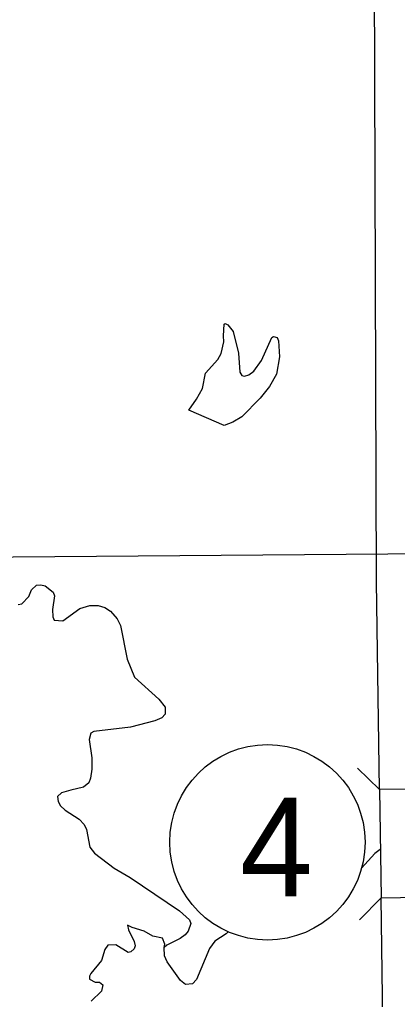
# Model space of a CAD drawing. Extents: x 982240 to 1103002, y 974866 to 1054902.
# Drawn here: x 1055765 to 1057609, y 1005692 to 1010471 of the extents above; entities that cross this region are included whole.
import ezdxf

# ---------------------------------------------------------------- set-up
doc = ezdxf.new("R2010")
doc.units = 0
for name, color, linetype in [('10', 7, 'Continuous'), ('35', 7, 'Continuous'), ('37', 7, 'Continuous'), ('5', 7, 'Continuous'), ('R_Draft', 7, 'Continuous')]:
    doc.layers.add(name, color=color, linetype=linetype)

msp = doc.modelspace()

# ---------------------------------------------------------------- linework, layer by layer
at = {"layer": '10'}
for p, q in [((1057771.9, 1006719.4), (1057521.9, 1006715.5)), ((1057529.2, 1006187.7), (1057779.2, 1006191.7))]:
    msp.add_line(p, q, dxfattribs=at)
for points in [[(1057521.9, 1006715.5), (1057507.8, 1007729.5), (1057490.8, 1012651.9), (1057440.6, 1017897.7), (1057430.5, 1017929.5), (1057356.9, 1018048.7)], [(1057521.9, 1006715.5), (1057529.2, 1006187.7)], [(1057577.8, 1002687.5), (1057529.2, 1006187.7)]]:
    msp.add_lwpolyline(points, dxfattribs=at)
at = {"layer": '35'}
for points in [[(1056591.5, 1008565.5), (1056629.2, 1008619.6), (1056657, 1008672.5), (1056672.3, 1008747.2), (1056732.8, 1008812.9), (1056749.2, 1008842.4), (1056761.8, 1008900), (1056760.1, 1008929.1), (1056762.8, 1008985.4), (1056768.7, 1008988.5), (1056780.9, 1008982.8), (1056806.7, 1008950.3), (1056834.3, 1008844.5), (1056839.5, 1008752.2), (1056850, 1008734.4), (1056863.1, 1008732.7), (1056883.9, 1008739.2), (1056907.6, 1008756.8), (1056946.4, 1008808), (1056996.8, 1008920.7), (1057004.8, 1008924.9), (1057022.9, 1008920.3), (1057029.3, 1008904.4), (1057034.2, 1008826.1), (1057019.2, 1008742.4), (1056985.6, 1008681.4), (1056938.8, 1008624), (1056849.8, 1008533.5), (1056805.3, 1008507.3), (1056763.6, 1008491.2)], [(1056763.6, 1008491.2), (1056591.5, 1008565.5)], [(1055758.3, 1007618.4), (1055775.2, 1007621.9), (1055810.5, 1007656.9), (1055823.7, 1007689.3), (1055847.2, 1007712), (1055868.2, 1007714.5), (1055890.4, 1007709), (1055928.2, 1007678.8), (1055935.7, 1007659.9), (1055926.2, 1007594.3), (1055927.1, 1007558.2), (1055934.5, 1007542.3), (1055975.7, 1007538.3), (1056059.4, 1007599.5), (1056108.2, 1007612.8), (1056148.3, 1007613.7), (1056180.6, 1007604.5), (1056209.1, 1007586.1), (1056241, 1007548.7), (1056257.9, 1007515.9), (1056289.9, 1007352), (1056325.1, 1007263.4), (1056443.9, 1007156.8), (1056475.9, 1007117.4), (1056475.7, 1007084.2), (1056460.1, 1007065.8), (1056424.4, 1007050.8), (1056305.9, 1007019.9), (1056128, 1006998.6), (1056113.1, 1006991.2), (1056103.9, 1006959.8), (1056118, 1006869.8), (1056117.3, 1006815.5), (1056111.4, 1006772.2), (1056102.9, 1006748.9), (1056077.4, 1006727.2), (1056014.6, 1006713.6), (1055968.8, 1006699.5), (1055950.2, 1006681.9), (1055952.8, 1006657.9), (1055965.3, 1006636.1), (1055987.8, 1006615.5), (1056055.1, 1006570.9), (1056080.7, 1006545.4), (1056091.3, 1006521.6), (1056108.4, 1006435.6), (1056130.2, 1006405), (1056226.2, 1006333), (1056304.4, 1006287.7)], [(1057525.6, 1006423.8), (1057498.3, 1006404.6), (1057433.9, 1006332.8), (1057433.5, 1006332.6)], [(1056304.4, 1006287.7), (1056544.9, 1006123.7), (1056595, 1006080.7), (1056600.5, 1006062.7), (1056588.3, 1006025.3), (1056573.8, 1006006.8), (1056549.1, 1005989.2), (1056483.7, 1005957.5), (1056470, 1005946.1), (1056473.6, 1005962.3), (1056462.9, 1005991.1), (1056415.5, 1006001), (1056372.9, 1006025.1), (1056315.3, 1006043.8), (1056292, 1006054.3), (1056296.5, 1006032.3), (1056324, 1005974.8), (1056329.5, 1005953.8), (1056323.8, 1005938.6), (1056308.1, 1005924.2), (1056294.2, 1005920.8), (1056235.2, 1005958.6), (1056196.1, 1005957.6), (1056181.6, 1005935.2), (1056164.8, 1005882.6), (1056112.2, 1005819), (1056106.5, 1005805.8), (1056106.9, 1005790.8), (1056133.3, 1005776.3), (1056155.4, 1005775.9), (1056170.7, 1005764.2), (1056164.4, 1005731.9), (1056114.5, 1005684.5)], [(1056782.8, 1006022.4), (1056774.1, 1006011.6), (1056718.8, 1005977.2), (1056691.6, 1005941.4), (1056628.1, 1005789.2), (1056608.6, 1005767.6), (1056575.5, 1005765.8), (1056550, 1005784.3), (1056484.7, 1005876.2), (1056472, 1005905), (1056470, 1005946.1)]]:
    msp.add_lwpolyline(points, dxfattribs=at)
at = {"layer": '37'}
for points in [[(1057521.9, 1006715.5), (1057414.2, 1006819.8)], [(1057424.9, 1006080), (1057529.2, 1006187.7)]]:
    msp.add_lwpolyline(points, dxfattribs=at)
at = {"layer": '5'}
msp.add_lwpolyline([(1060404.3, 1007887.4), (1054920, 1007843.4), (1053378.4, 1007824.8)], dxfattribs=at)
at = {"layer": 'R_Draft'}
msp.add_circle((1056974.5, 1006458.6), 476.6, dxfattribs=at)

# ---------------------------------------------------------------- texts
msp.add_text('4', height=480, dxfattribs=at).set_placement((1056840, 1006195.8))

doc.saveas('drawing.dxf')
